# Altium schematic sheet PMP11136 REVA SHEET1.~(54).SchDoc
size 431 x 279 mm; Date: Not shown in title block; ApprovedBy: Not shown in title block; CheckedBy: Not shown in title block; Author: Not shown in title block; CompanyName: Not shown in title block; Engineer: Not shown in title block; Organization: Not shown in title block; Address1: Not shown in title block; Address2: Not shown in title block; Address3: Not shown in title block; Address4: Not shown in title block; DocumentNumber: 1; Revision: Use project parameter SCH_Rev; SheetNumber: 1; SheetTotal: 3; PageSetup: Record=PageOptions¦CenterHorizontal=True¦CenterVertical=True¦PrintScale=1.00¦XCorrection=1.00¦YCorrection=1.00¦PrintKind=0¦BorderSize=5000000¦LeftOffset=0¦BottomOffset=0¦Orientation=2¦PaperLength=1000¦PaperWidth=1000¦Scale=100¦PaperSource=15¦PrintQuality=600¦MediaType=1¦DitherType=10¦PaperKind=Letter¦PrintScaleMode=1
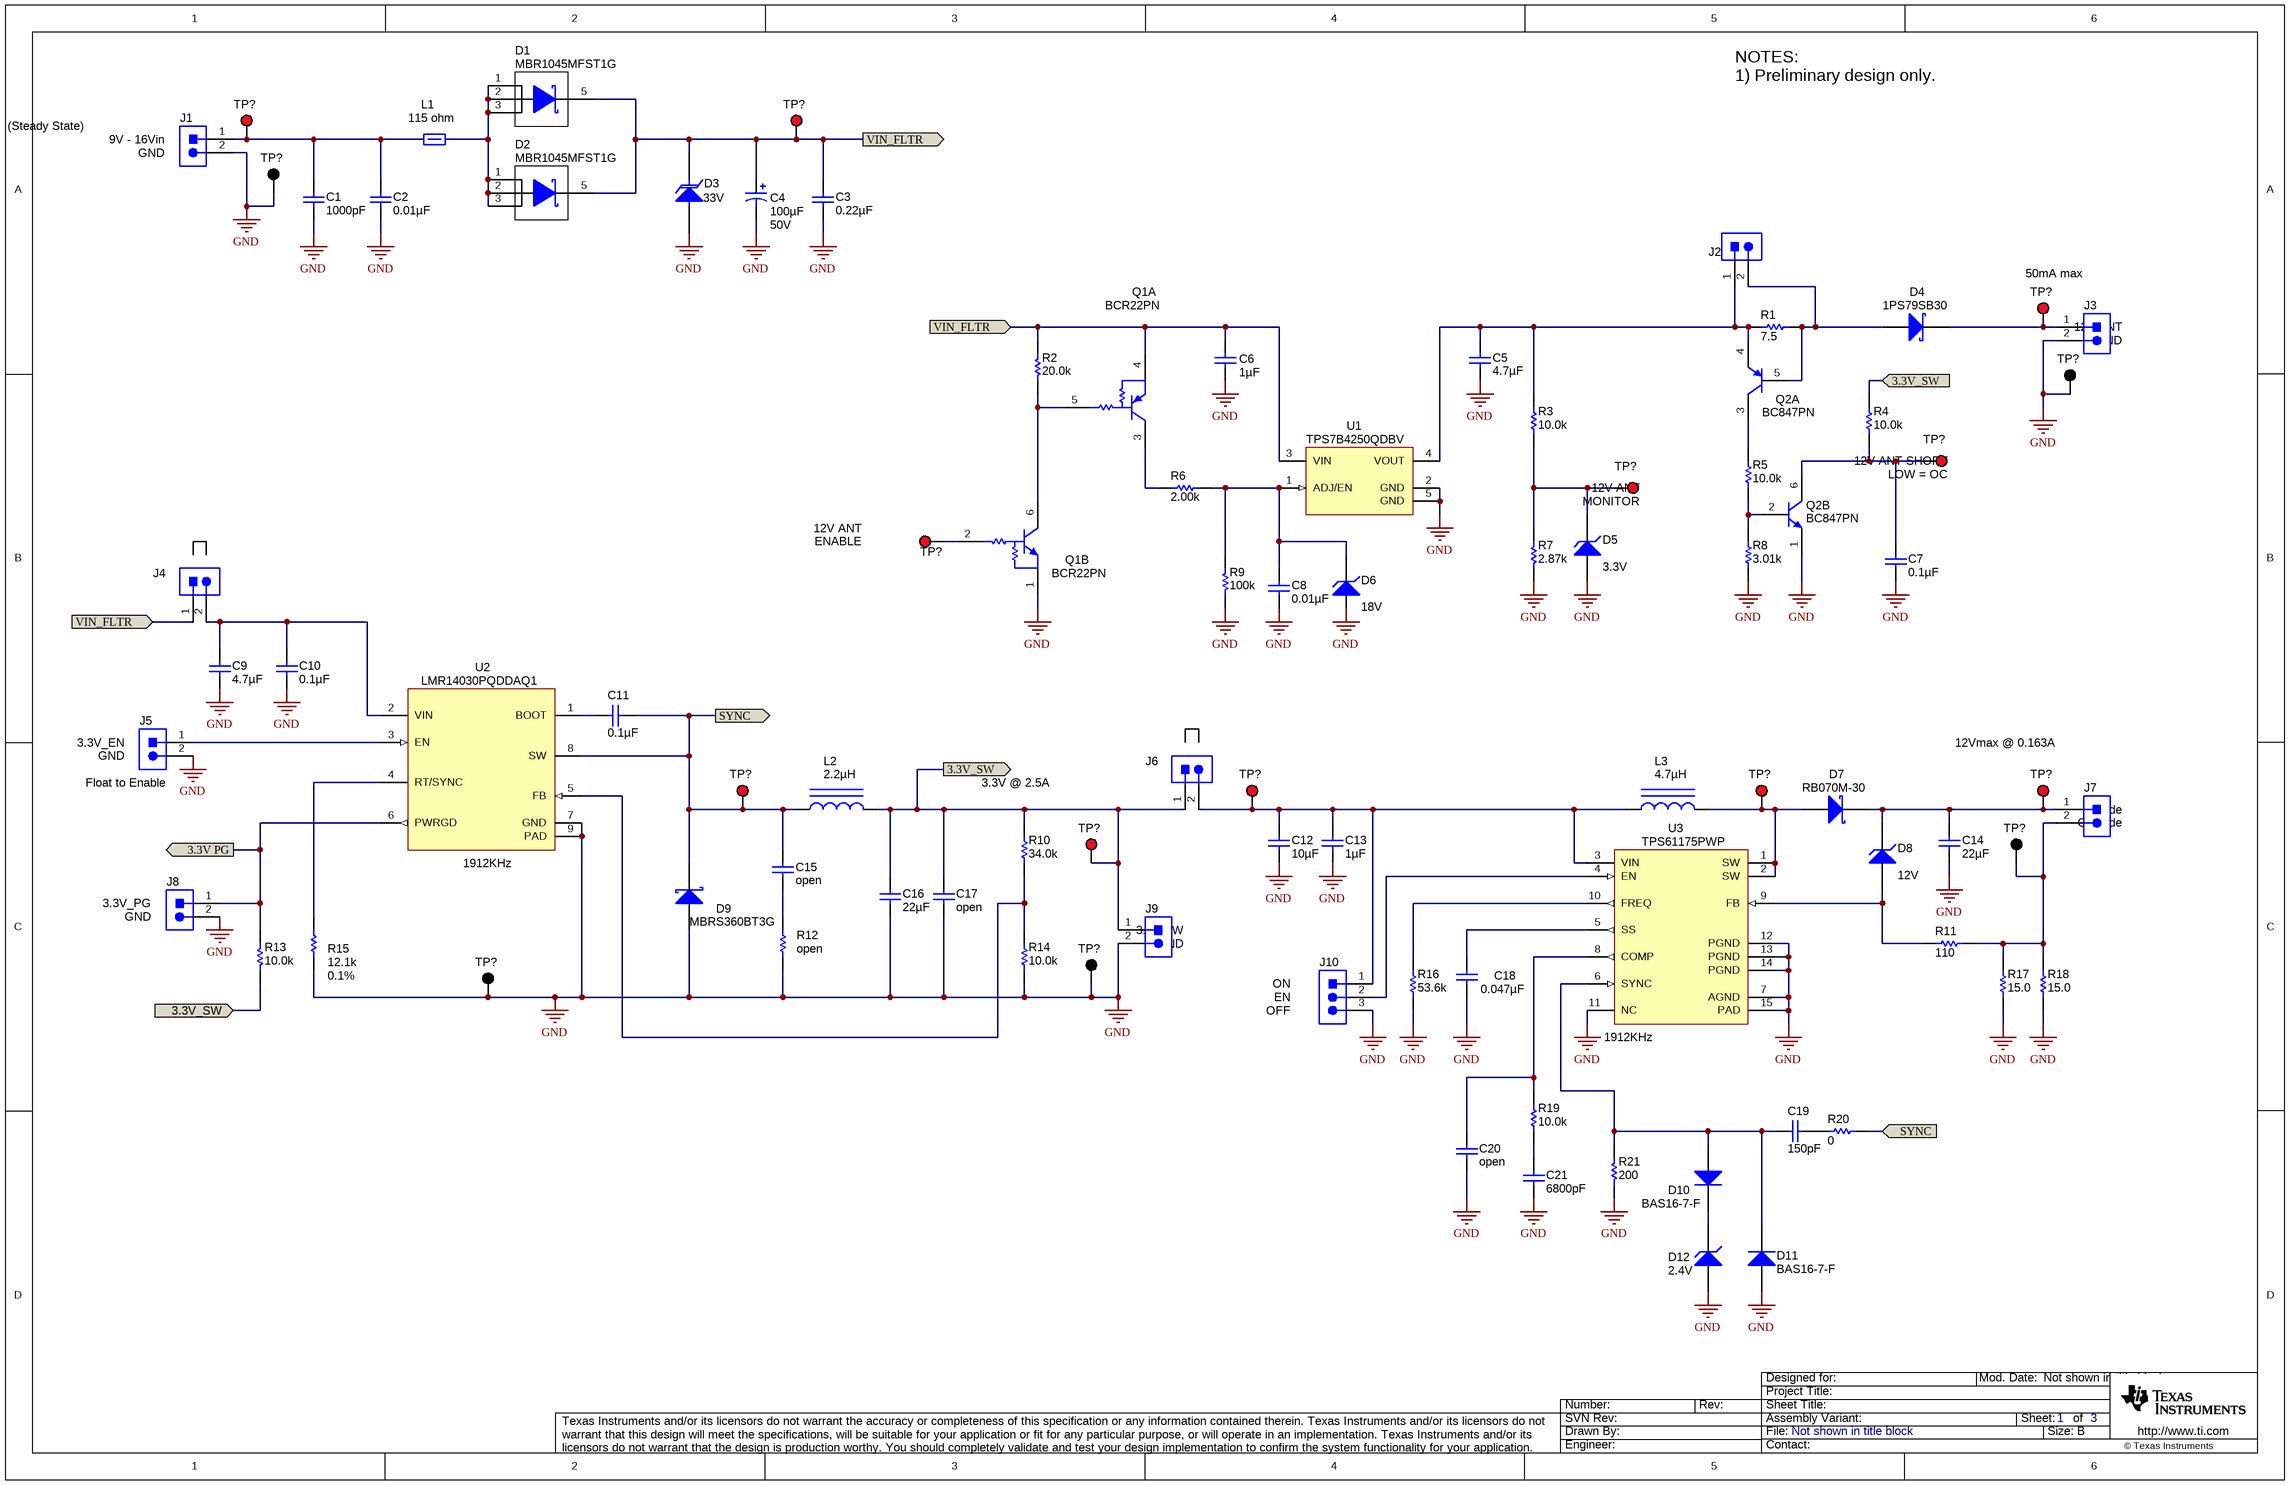
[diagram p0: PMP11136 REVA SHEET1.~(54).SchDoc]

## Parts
(Parts that share a designator on the sheet are numbered #1, #2 ... from top to bottom, then left to right.)
C1  ValueDisplayed: 1000pF  [0603]  (hidden comment: C1608C0G2A102J)
C2  ValueDisplayed: 0.01µF  [0603]  (hidden comment: C1608X7R2A103K)
C3  ValueDisplayed: 0.22µF  [0603]  (hidden comment: C1608X7R1H224K080AB)
C4  ValueDisplayed: 100µF  Value2: 50V  [SM_RADIAL_F]  (hidden comment: EEE-FK1H101P)
C5  ValueDisplayed: 4.7µF  [1210]  (hidden comment: C3225X7R1H475M250AB)
C6  ValueDisplayed: 1µF  [0603]  (hidden comment: C1608X7R1E105K)
C7  ValueDisplayed: 0.1µF  [0603]  (hidden comment: C1608X7R1H104K)
C8  ValueDisplayed: 0.01µF  [0603]  (hidden comment: C1608X7R1H103K)
C9  ValueDisplayed: 4.7µF  [1210]  (hidden comment: C3225X7R1H475M250AB)
C10  ValueDisplayed: 0.1µF  [0603]  (hidden comment: C1608X7R1H104K)
C11  ValueDisplayed: 0.1µF  [0603]  (hidden comment: C1608X7R1H104K)
C12  ValueDisplayed: 10µF  [0805]  (hidden comment: GRM21BR71A106KE51L)
C13  ValueDisplayed: 1µF  [0603]  (hidden comment: C1608X7R1E105K)
C14  ValueDisplayed: 22µF  [1210]  (hidden comment: C3225X7R1C226M250AC)
C15  ValueDisplayed: open  [0603]
C16  ValueDisplayed: 22µF  [1210]  (hidden comment: C3225X7R1C226M250AC)
C17  ValueDisplayed: open  [1210]
C18  ValueDisplayed: 0.047µF  [0603]  (hidden comment: C1608X7R1H473K)
C19  ValueDisplayed: 150pF  [0603]  (hidden comment: C1608C0G1H151J)
C20  ValueDisplayed: open  [0603]
C21  ValueDisplayed: 6800pF  [0603]  (hidden comment: C1608C0G1E682J)
D1  MBR1045MFST1G  [SO-8FL]
D2  MBR1045MFST1G  [SO-8FL]
D3  value 33V  [SMC]  (hidden comment: 1.5SMC33AT3G)
D4  1PS79SB30  [SOD-523]
D5  value 3.3V  [SOD-123]  (hidden comment: MMSZ4684T1G)
D6  value 18V  [SOD-123]  (hidden comment: MMSZ4705T1G)
D7  RB070M-30  [SOD-123]
D8  value 12V  [SOD-123]  (hidden comment: MMSZ4699T1G)
D9  MBRS360BT3G  [SMB]
D10  BAS16-7-F  [SOT-23]
D11  BAS16-7-F  [SOT-23]
D12  value 2.4V  [SOD-123]  (hidden comment: MMSZ5221B-7-F)
J1  ED555/2DS  [TERM_BLK_ED555-2DS]  (value not drawn)
J2  PEC02SAAN  [CONN_PEC02SAAN]  (value not drawn)
J3  ED555/2DS  [TERM_BLK_ED555-2DS]  (value not drawn)
J4  PEC02SAAN  [CONN_PEC02SAAN]  (value not drawn)
J5  PEC02SAAN  [CONN_PEC02SAAN]  (value not drawn)
J6  PEC02SAAN  [CONN_PEC02SAAN]  (value not drawn)
J7  ED555/2DS  [TERM_BLK_ED555-2DS]  (value not drawn)
J8  PEC02SAAN  [CONN_PEC02SAAN]  (value not drawn)
J9  ED555/2DS  [TERM_BLK_ED555-2DS]  (value not drawn)
J10  PEC03SAAN  [CONN_PEC03SAAN]  (value not drawn)
L1  value 115 ohm  [28F0181]  (hidden comment: 28F0181-1SR-10)
L2  ValueDisplayed: 2.2µH  [CLF6045NI-D]  (hidden comment: CLF6045NIT-2R2N-D)
L3  ValueDisplayed: 4.7µH  [CLF6045NI-D]  (hidden comment: CLF6045NIT-4R7N-D)
Q1  BCR22PN  [SOT-363]  (parts A,B of 2)
Q2  BC847PN  [SOT-363]  (parts A,B of 2)
R1  ValueDisplayed: 7.5  [2010]  (hidden comment: CRCW20107R50JNEF)
R2  ValueDisplayed: 20.0k  [0603]  (hidden comment: CRCW060320K0FKEA)
R3  ValueDisplayed: 10.0k  [0603]  (hidden comment: CRCW060310K0FKEA)
R4  ValueDisplayed: 10.0k  [0603]  (hidden comment: CRCW060310K0FKEA)
R5  ValueDisplayed: 10.0k  [0805_HV]  (hidden comment: CRCW080510K0FKEA)
R6  ValueDisplayed: 2.00k  [1206]  (hidden comment: CRCW12062K00FKEA)
R7  ValueDisplayed: 2.87k  [0603]  (hidden comment: CRCW06032K87FKEA)
R8  ValueDisplayed: 3.01k  [0603]  (hidden comment: CRCW06033K01FKEA)
R9  ValueDisplayed: 100k  [0603]  (hidden comment: CRCW0603100KFKEA)
R10  ValueDisplayed: 34.0k  [0603]  (hidden comment: CRCW060334K0FKEA)
R11  ValueDisplayed: 110  [0603]  (hidden comment: CRCW0603110RFKEA)
R12  value open  [2010]
R13  ValueDisplayed: 10.0k  [0603]  (hidden comment: CRCW060310K0FKEA)
R14  ValueDisplayed: 10.0k  [0603]  (hidden comment: CRCW060310K0FKEA)
R15  Value1: 0.1%  ValueDisplayed: 12.1k  [0603]
R16  ValueDisplayed: 53.6k  [0603]  (hidden comment: CRCW060353K6FKEA)
R17  ValueDisplayed: 15.0  [1206]  (hidden comment: CRCW120615R0FKEA)
R18  ValueDisplayed: 15.0  [1206]  (hidden comment: CRCW120615R0FKEA)
R19  ValueDisplayed: 10.0k  [0603]  (hidden comment: CRCW060310K0FKEA)
R20  ValueDisplayed: 0  [0603]  (hidden comment: CRCW06030000Z0EA)
R21  ValueDisplayed: 200  [0603]  (hidden comment: CRCW0603200RFKEA)
TP?#1  5000  [Keystone5000]  (value not drawn)
TP?#2  5000  [Keystone5000]  (value not drawn)
TP?#3  5001  [Keystone5001]  (value not drawn)
TP?#4  5000  [Keystone5000]  (value not drawn)
TP?#5  5001  [Keystone5001]  (value not drawn)
TP?#6  5000  [Keystone5000]  (value not drawn)
TP?#7  5000  [Keystone5000]  (value not drawn)
TP?#8  5000  [Keystone5000]  (value not drawn)
TP?#9  5000  [Keystone5000]  (value not drawn)
TP?#10  5000  [Keystone5000]  (value not drawn)
TP?#11  5000  [Keystone5000]  (value not drawn)
TP?#12  5000  [Keystone5000]  (value not drawn)
TP?#13  5000  [Keystone5000]  (value not drawn)
TP?#14  5001  [Keystone5001]  (value not drawn)
TP?#15  5001  [Keystone5001]  (value not drawn)
TP?#16  5001  [Keystone5001]  (value not drawn)
U1  TPS7B4250QDBV  [DBV0005A_N]
U2  LMR14030PQDDAQ1  [DDA0008E_N]
U3  TPS61175PWP  [PWP0014E_N]

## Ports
3.3V PG, 3.3V_SW, SYNC, VIN_FLTR

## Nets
GND: C1.2 C2.2 C3.2 C4.2(-) C5.1 C6.2 C7.2 C8.2 C9.1 C10.2 C12.2 C13.2 C14.2 C16.2 C17.2 C18.2 C20.2 C21.2 D3.2(A) D5.2(A) D9.2(A) D11.1(A) D12.2(A) J1.2 J3.2 J5.2 J8.2 J9.2 J10.3 Q1.1(E1) Q2.1(E) R7.2 R8.1 R9.2 R12.1 R14.1 R15.1 R16.1 R17.1 R18.1 R21.1 TP?#3.1 TP?#5.1 TP?#15.1 TP?#16.1 U1.2(GND) U1.5(GND) U2.7(GND) U2.9(PAD) U3.7(AGND) U3.11(NC) U3.12(PGND) U3.13(PGND) U3.14(PGND) U3.15(PAD)
3.3V PG: J8.1 R13.2 U2.6(PWRGD) ; port 3.3V PG
3.3V_SW: C16.1 C17.1 J6.1 J9.1 L2.2 R4.2 R10.2 R13.1 TP?#13.1 ; port 3.3V_SW
SYNC: C11.2 C15.1 D9.1(K) L2.1 R20.1 TP?#9.1 U2.8(SW) ; port SYNC
VIN_FLTR: C3.1 C4.1(+) C6.1 D1.5(K) D2.5(K) D3.1(K) J4.1 Q1.4(E2) R2.2 TP?#2.1 U1.3(VIN) ; port VIN_FLTR
NetC1_1: C1.1 C2.1 J1.1 L1.1 TP?#1.1
NetC5_2: C5.2 J2.1 Q2.4(E) R1.1 R3.2 U1.4(VOUT)
NetC7_1: C7.1 Q2.6(C) R4.1 TP?#6.1
NetC8_1: C8.1 D6.1(K) R6.2 R9.1 U1.1(ADJ/EN)
NetC9_2: C9.2 C10.1 J4.2 U2.2(VIN)
NetC11_1: C11.1 U2.1(BOOT)
NetC12_1: C12.1 C13.1 J6.2 J10.1 L3.1 TP?#10.1 U3.3(VIN)
NetC14_1: C14.1 D7.1(K) D8.1(K) J7.1 TP?#12.1
NetC15_2: C15.2 R12.2
NetC18_1: C18.1 U3.5(SS)
NetC19_1: C19.1 D10.1(A) D11.3(K) R21.2 U3.6(SYNC)
NetC19_2: C19.2 R20.2
NetC20_1: C20.1 R19.2 U3.8(COMP)
NetC21_1: C21.1 R19.1
NetD1_1: D1.1(A) D1.2(A) D1.3(A) D2.1(A) D2.2(A) D2.3(A) L1.2
NetD4_1: D4.1(K) J3.1 TP?#4.1
NetD4_2: D4.2(A) J2.2 Q2.5(B) R1.2
NetD5_1: D5.1(K) R3.1 R7.1 TP?#7.1
NetD7_2: D7.2(A) L3.2 TP?#11.1 U3.1(SW) U3.2(SW)
NetD8_2: D8.2(A) R11.2 U3.9(FB)
NetD10_3: D10.3(K) D12.1(K)
NetJ5_1: J5.1 U2.3(EN)
NetJ7_2: J7.2 R11.1 R17.2 R18.2 TP?#14.1
NetJ10_2: J10.2 U3.4(EN)
NetQ1_2: Q1.2(B1) TP?#8.1
NetQ1_3: Q1.3(C2) R6.1
NetQ1_5: Q1.5(B2) Q1.6(C1) R2.1
NetQ2_2: Q2.2(B) R5.1 R8.2
NetQ2_3: Q2.3(C) R5.2
NetR10_1: R10.1 R14.2 U2.5(FB)
NetR15_2: R15.2 U2.4(RT/SYNC)
NetR16_2: R16.2 U3.10(FREQ)

Not connected (* = marked no-connect by the designer): D6 2(A)

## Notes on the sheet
- (near J1) (Steady State)
- (near J1) 9V - 16Vin
- (near J1) GND
- NOTES:
  1) Preliminary design only.
- 50mA max
- (near J3) 12V ANT
- GND
- (near TP?#7) MONITOR
- (near TP?#7) 12V ANT
- (near TP?#6) LOW = OC
- (near TP?#6) 12V ANT SHORT
- (near TP?#8) ENABLE
- (near TP?#8) 12V ANT
- (near J5) 3.3V_EN
- (near J5) GND
- 12Vmax @ 0.163A
- (near J5) Float to Enable
- 3.3V @ 2.5A
- (near J7) Anode
- (near J7) Cathode
- (near J8) 3.3V_PG
- (near U2) 1912KHz
- (near J8) GND
- (near J9) 3.3V SW
- (near J9) GND
- (near J10) ON
- (near J10) EN
- (near J10) OFF
- (near U3) 1912KHz
- Labels drawn without touching a wire or pin: GND

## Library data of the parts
C1 = C1608C0G2A102J: CAP, CERM, 1000 pF, 100 V, +/- 5%, C0G/NP0, 0603; Manufacturer: TDK; Polarized: N; CompType: Capacitor; Value: 1000pF; U/M: EA; Cap_F: 0.000000001; Tolerance_%: 5; ESR_ohm: 0.0589; Value1: 0.0589 ohm; VDC_V: 100; Value2: 100V; TaMin_C: -55; TaMax_C: 125
C2 = C1608X7R2A103K: CAP, CERM, 0.01 µF, 100 V, +/- 10%, X7R, 0603; Manufacturer: TDK; Polarized: N; CompType: Capacitor; Value: 0.01uF; U/M: EA; Cap_F: 0.00000001; Tolerance_%: 10; ESR_ohm: 0.0661; Value1: 0.0661 ohm; VDC_V: 100; Value2: 100V; TaMin_C: -55; TaMax_C: 125
C3 = C1608X7R1H224K080AB: CAP, CERM, 0.22 µF, 50 V, +/- 10%, X7R, 0603; Manufacturer: TDK; Polarized: N; CompType: Capacitor; Value: 0.22uF; U/M: EA; Cap_F: 0.00000022; Tolerance_%: 10; Value1: Unknown; VDC_V: 50; Value2: 50V; TaMin_C: -55; TaMax_C: 125
C4 = EEE-FK1H101P: CAP, AL, 100 µF, 50 V, +/- 20%, 0.34 ohm, SMD; Manufacturer: Panasonic; Polarized: Y; CompType: Capacitor; Value: 100uF; U/M: EA; Cap_F: 0.0001; Tolerance_%: 20; VDC_V: 50; ESR_ohm: 0.34; IRMS_A: 0.35; TaMin_C: -55; TaMax_C: 105; Cap_Case: F
C5 C9 = C3225X7R1E106M: CAP, CERM, 4.7uF, 50V, +/-20%, X7R, 1210; Manufacturer: TDK; Polarized: N; CompType: Capacitor; U/M: EA; Cap_F: 0.00001; Tolerance_%: 20; ESR_Ohm: 0.0027; Value1: 0.0027 ohm; VDC_V: 50; IRMS_A: 3; TaMin_C: -55; TaMax_C: 125
C6 C13 = C1608X7R1C105K: CAP, CERM, 1uF, 25V, +/-10%, X7R, 0603; Manufacturer: TDK; Polarized: N; CompType: Capacitor; U/M: EA; Cap_F: 0.000001; Tolerance_%: 10; ESR_Ohm: 0.0057; Value1: 0.0057 ohm; VDC_V: 25; TaMin_C: -55; TaMax_C: 125
C7 C10 C11 = C1608X7R1H104K: CAP, CERM, 0.1uF, 50V, +/-10%, X7R, 0603; Manufacturer: TDK; Polarized: N; CompType: Capacitor; U/M: EA; Cap_F: 0.0000001; Tolerance_%: 10; ESR_Ohm: 0.017; Value1: 0.017 ohm; VDC_V: 50; TaMin_C: -55; TaMax_C: 125
C8 = C1608X7R1H103K: CAP, CERM, 0.01 µF, 50 V, +/- 10%, X7R, 0603; Manufacturer: TDK; Polarized: N; CompType: Capacitor; Value: 0.01uF; U/M: EA; Cap_F: 0.00000001; Tolerance_%: 10; ESR_ohm: 0.0539; Value1: 0.0539 ohm; VDC_V: 50; Value2: 50V; TaMin_C: -55; TaMax_C: 125
C12 = GRM21BR71A106KE51L: CAP, CERM, 10uF, 10V, +/-10%, X7R, 0805; Manufacturer: MuRata; Polarized: N; CompType: Capacitor; U/M: EA; Cap_F: 0.00001; Tolerance_%: 10; ESR_Ohm: 0.003; Value1: 0.003 ohm; TaMin_C: -55; TaMax_C: 125
C14 C16 = C3225X7R1C226M: CAP, CERM, 22 µF, 16 V, +/- 20%, X7R, 1210; Manufacturer: TDK; Polarized: N; CompType: Capacitor; Value: 22uF; U/M: EA; Cap_F: 0.000022; Tolerance_%: 20; ESR_ohm: 0.002; Value1: 0.002 ohm; VDC_V: 16; Value2: 16V; IRMS_A: 8.11; TaMin_C: -55; TaMax_C: 125
C15 C20 = C1608C0G1H102J: CAP, CERM, open, 0603; Polarized: N; CompType: Capacitor; U/M: EA; Cap_F: 0.000000001; Tolerance_%: 5; ESR_ohm: 0.0563; TempCo: C0G/NP0; TaMin_C: -55; TaMax_C: 125
C17 = C3225X7R1C226M: CAP, open, 1210; Polarized: N; CompType: Capacitor; U/M: EA; Cap_F: 0.000022; Tolerance_%: 20; ESR_ohm: 0.002; TempCo: X7R; IRMS_A: 8.11; TaMin_C: -55; TaMax_C: 125
C18 = C1608X7R1H473K: CAP, CERM, 0.047 µF, 50 V, +/- 10%, X7R, 0603; Manufacturer: TDK; Polarized: N; CompType: Capacitor; Value: 0.047uF; U/M: EA; Cap_F: 0.000000047; Tolerance_%: 10; ESR_ohm: 0.0234; Value1: 0.0234 ohm; VDC_V: 50; Value2: 50V; TaMin_C: -55; TaMax_C: 125
C19 = C1608C0G1H151J: CAP, CERM, 150 pF, 50 V, +/- 5%, C0G/NP0, 0603; Manufacturer: TDK; Polarized: N; CompType: Capacitor; Value: 150pF; U/M: EA; Cap_F: 0.00000000015; Tolerance_%: 5; ESR_ohm: 0.1084; Value1: 0.1084 ohm; VDC_V: 50; Value2: 50V; TaMin_C: -55; TaMax_C: 125
C21 = C1608C0G1E682J: CAP, CERM, 6800 pF, 25 V, +/- 5%, C0G/NP0, 0603; Manufacturer: TDK; Polarized: N; CompType: Capacitor; Value: 6800pF; U/M: EA; Cap_F: 0.0000000068; Tolerance_%: 5; Value1: Unknown; VDC_V: 25; Value2: 25V; TaMin_C: -55; TaMax_C: 125
D1 D2 = MBR1045MFST1G: Diode, Schottky, 45 V, 10 A, 6.15x1.00x5.15mm; Manufacturer: ON Semiconductor; SymbolCreator: a0411947; U/M: EA; Vf_V: 0.62; Value: 45V; Value1: 10A; Value2: 0.62V; Io_A: 10; Vr_V: 45; TJmax_C: 150; RJC_CperW: 1.7
D3 = 1.5SMC6.8A: Diode, TVS, Uni, 33 V, 1500 W, SMC; Manufacturer: Littelfuse; U/M: EA; Power_W: 1500; Vr_V: 33; Value1: 1500W; RJA_CperW: 75
D4 = 1PS79SB70,115: Diode, Schottky, 30 V, 0.2 A, SOD-523; Manufacturer: NXP; U/M: EA; Value: 30V; Value1: 0.2A; Io_A: 0.07; TJmax_C: 150
D5 = MMSZ4684T1G: Diode, Zener, 3.3 V, 500 mW, SOD-123; Manufacturer: ON Semiconductor; SymbolCreator: a0412235; U/M: EA; Power_W: 0.5; Vz_V: 3.3; Value1: 0.5W; RJA_CperW: 340
D6 = MMSZ4705T1G: Diode, Zener, 18 V, 500 mW, SOD-123; Manufacturer: ON Semiconductor; SymbolCreator: a0412235; U/M: EA; Power_W: 0.5; Vz_V: 18; Value1: 0.5W; RJA_CperW: 340
D7 = B130LAW-7-F: Diode, Schottky, 30V, 1.5A, SOD-123; Manufacturer: Rohm; U/M: EA; Vf_V: 0.38; Value1: 1A; Value2: 0.38V; Io_A: 1.5; Vr_V: 30; TJmax_C: 125
D8 = MMSZ4699T1G: Diode, Zener, 12 V, 500 mW, SOD-123; Manufacturer: ON Semiconductor; SymbolCreator: a0412235; U/M: EA; Power_W: 0.5; Vz_V: 12; Value1: 0.5W; RJA_CperW: 340
D9 = MBRS260T3G: Diode, Schottky, 60V, 3A, SMB; Manufacturer: ON Semiconductor; U/M: EA; Vf_V: 0.63; Value2: 0.63V; Io_A: 2; Vr_V: 60; TJmax_C: 125; RJC_CperW: 24
D10 D11 = BAS16-7-F: Diode, Ultrafast, 75V, 0.3A, SOT-23; Manufacturer: Diodes Inc.; U/M: EA; Vf_V: 1.125; Value2: 1.125V; Io_A: 0.3; Vr_V: 75
D12 = MMSZ5221B-7-F: Diode, Zener, 2.4V, 500 mW, SOD-123; Manufacturer: Diodes Inc.; SymbolCreator: a0412235; U/M: EA; Power_W: 0.5; Vz_V: 2.4; Value1: 0.5W; RJA_CperW: 350
J1 J3 J7 J9 = ED555/2DS: Terminal Block, 6A, 3.5mm Pitch, 2-Pos, TH; Manufacturer: On-Shore Technology; SymbolCreator: a0412235; CompType: Connector; U/M: EA
J2 J4-J6 J8 = PEC02SAAN: Header, 100mil, 2x1, Tin, TH; Manufacturer: Sullins Connector Solutions; SymbolCreator: a0412235; U/M: EA
J10 = PEC03SAAN: Header, 100mil, 3x1, Tin, TH; Manufacturer: Sullins Connector Solutions; SymbolCreator: a0799628; U/M: EA
L1 = 28F0181-1SR-10: Ferrite Bead, 115 ohm @ 100MHz, 10A, SMD, 2-Leads, Body 8.74x4.65mm; Manufacturer: Laird-Signal Integrity Products; Imax_A: 10; DCR_ohm: 0.001; Value1: 0.001 ohm; ZTyp@100MHz_Ohm: 115
L2 = CLF6045NIT-2R2N-D: Inductor, Wirewound, Ferrite, 2.2 µH, 4.1 A, 0.015 ohm, SMD; Manufacturer: TDK; Value: 2.2uH; Ind_H: 2.2E-6; Imax_A: 4.1; Irms: 4.1A @ 40C rise; Isat: 4.2A @ 30% inductance drop; DCR_ohm: 0.015; Value2: 4.1A
L3 = CLF6045NIT-4R7N-D: Inductor, Wirewound, Ferrite, 4.7 µH, 3.1 A, 0.023 ohm, SMD; Manufacturer: TDK; Value: 4.7uH; Ind_H: 4.7E-6; Imax_A: 3.1; Irms: 3.3A @ 40C rise; Isat: 3.1A @ 30% inductance drop; DCR_ohm: 0.023; Value2: 3.1A
Q1 = BCR 48PN E6327, Infineon Technologies: Transistor, NPN/PNP Pair, 50 V, 0.1 A, SOT-363; SymbolCreator: Altium; PNP: 1; Vceo_V: 50; Vcesat1_V: 0.3; Value: 50 V; IcRated_A: 0.07; Value1: 0.1 A; TaMin_C: -65; TaMax_C: 150; CompType: BJT; U/M: EA
Q2 = BC 846PN H6327, Infineon Technologies: Transistor, NPN/PNP Pair, 45 V, 0.1 A, SOT-363; SymbolCreator: a0411947; PNP: 1; Vceo_V: 45; Vcesat1_V: 0.2; Value: 45 V; IcRated_A: 0.1; Value1: 0.1 A; HfeMax: 450; TaMin_C: -65; TaMax_C: 150; CompType: BJT; U/M: EA
R1 = CRCW20107R50JNEF: RES, 7.5, 5%, 0.75 W, 2010; Manufacturer: Vishay-Dale; CompType: Resistor; Value: 7.5; Value_Code: 7R50; Tolerance_%: 5; Power_W: 0.75; Value2: 0.75W; VDC_V: 400; TempCo: 200 ppm/C; EIA_Code: E24; U/M: EA
R2 = CRCW060320K0FKEA: RES, 20.0 k, 1%, 0.1 W, 0603; Manufacturer: Vishay-Dale; CompType: Resistor; Value: 20.0k; Res_ohm: 20000; Value_Code: 20k0; Tolerance_%: 1; Power_W: 0.1; Value2: 0.1W; VDC_V: 75; TempCo: 100 ppm/C; EIA_Code: E96; U/M: EA
R3 R4 R13 R14 R19 = CRCW060310K0FKEA: RES, 10.0 k, 1%, 0.1 W, 0603; Manufacturer: Vishay-Dale; CompType: Resistor; Value: 10.0k; Res_ohm: 10000; Value_Code: 10k0; Tolerance_%: 1; Power_W: 0.1; Value2: 0.1W; VDC_V: 75; TempCo: 100 ppm/C; EIA_Code: E96; U/M: EA
R5 = CRCW080510K0FKEA: RES, 10.0 k, 1%, 0.125 W, 0805; Manufacturer: Vishay-Dale; CompType: Resistor; Value: 10.0k; Res_ohm: 10000; Value_Code: 10k0; Tolerance_%: 1; Power_W: 0.125; Value2: 0.125W; VDC_V: 150; TempCo: 100 ppm/C; EIA_Code: E96; U/M: EA
R6 = CRCW12062K00FKEA: RES, 2.00 k, 1%, 0.25 W, 1206; Manufacturer: Vishay-Dale; CompType: Resistor; Value: 2.00k; Res_ohm: 2000; Value_Code: 2k00; Tolerance_%: 1; Power_W: 0.25; Value2: 0.25W; VDC_V: 200; TempCo: 100 ppm/C; EIA_Code: E96; U/M: EA
R7 = CRCW06032K87FKEA: RES, 2.87 k, 1%, 0.1 W, 0603; Manufacturer: Vishay-Dale; CompType: Resistor; Value: 2.87k; Res_ohm: 2870; Value_Code: 2k87; Tolerance_%: 1; Power_W: 0.1; Value2: 0.1W; VDC_V: 75; TempCo: 100 ppm/C; EIA_Code: E96; U/M: EA
R8 = CRCW06033K01FKEA: RES, 3.01 k, 1%, 0.1 W, 0603; Manufacturer: Vishay-Dale; CompType: Resistor; Value: 3.01k; Res_ohm: 3010; Value_Code: 3k01; Tolerance_%: 1; Power_W: 0.1; Value2: 0.1W; VDC_V: 75; TempCo: 100 ppm/C; EIA_Code: E96; U/M: EA
R9 = CRCW0603100KFKEA: RES, 100 k, 1%, 0.1 W, 0603; Manufacturer: Vishay-Dale; CompType: Resistor; Value: 100k; Res_ohm: 100000; Tolerance_%: 1; Power_W: 0.1; Value2: 0.1W; VDC_V: 75; TempCo: 100 ppm/C; EIA_Code: E96; U/M: EA
R10 = CRCW060334K0FKEA: RES, 34.0 k, 1%, 0.1 W, 0603; Manufacturer: Vishay-Dale; CompType: Resistor; Value: 34.0k; Res_ohm: 34000; Value_Code: 34k0; Tolerance_%: 1; Power_W: 0.1; Value2: 0.1W; VDC_V: 75; TempCo: 100 ppm/C; EIA_Code: E96; U/M: EA
R11 = CRCW0603110RFKEA: RES, 110, 1%, 0.1 W, 0603; Manufacturer: Vishay-Dale; CompType: Resistor; Value: 110; Value_Code: 110R; Tolerance_%: 1; Power_W: 0.1; Value2: 0.1W; VDC_V: 75; TempCo: 100 ppm/C; EIA_Code: E96; U/M: EA
R12 = CRCW20102R70JNEF: RES, open, 2010; CompType: Resistor; Tolerance_%: 5; Power_W: 0.75; TempCo: 200 ppm/C; EIA_Code: E24; U/M: EA
R15 = CRCW060312K1FKEA: RES, 12.1 k, 0.1%, 0.1 W, 0603; Manufacturer: Vishay-Dale; CompType: Resistor; Value: 12.1k; Res_ohm: 12100; Value_Code: 12k1; Tolerance_%: 1; Power_W: 0.1; Value2: 0.1W; VDC_V: 75; TempCo: 100 ppm/C; EIA_Code: E96; U/M: EA
R16 = CRCW060353K6FKEA: RES, 53.6 k, 1%, 0.1 W, 0603; Manufacturer: Vishay-Dale; CompType: Resistor; Value: 53.6k; Res_ohm: 53600; Value_Code: 53k6; Tolerance_%: 1; Power_W: 0.1; Value2: 0.1W; VDC_V: 75; TempCo: 100 ppm/C; EIA_Code: E96; U/M: EA
R17 R18 = CRCW120615R0FKEA: RES, 15.0, 1%, 0.25 W, 1206; Manufacturer: Vishay-Dale; CompType: Resistor; Value: 15.0; Res_ohm: 15; Value_Code: 15R0; Tolerance_%: 1; Power_W: 0.25; Value2: 0.25W; VDC_V: 200; TempCo: 100 ppm/C; EIA_Code: E96; U/M: EA
R20 = CRCW06030000Z0EA: RES, 0, 5%, 0.1 W, 0603; Manufacturer: Vishay-Dale; CompType: Resistor; Value: 0; Value_Code: 0000; Tolerance_%: 5; Power_W: 0.1; Value2: 0.1W; VDC_V: 75; TempCo: 200 ppm/C; EIA_Code: E24; U/M: EA
R21 = CRCW0603200RFKEA: RES, 200, 1%, 0.1 W, 0603; Manufacturer: Vishay-Dale; CompType: Resistor; Value: 200; Value_Code: 200R; Tolerance_%: 1; Power_W: 0.1; Value2: 0.1W; VDC_V: 75; TempCo: 100 ppm/C; EIA_Code: E96; U/M: EA
TP?#1 TP?#2 TP?#4 TP?#6-TP?#13 = 5000: Test Point, Miniature, Red, TH; Manufacturer: Keystone; CompType: Test Point Loop; U/M: EA
TP?#3 TP?#5 TP?#14-TP?#16 = 5001: Test Point, Miniature, Black, TH; Manufacturer: Keystone; CompType: Test Point Loop; U/M: EA
U1 = TPS7B4250QDBV: Low Dropout Voltage Tracking LDO, DBV0005A; Manufacturer: Texas Instruments; SymbolCreator: a0411947; CompType: IC; U/M: EA
U2 = LMR14030PDDAR: LMR14030PQDDAQ1, DDA0008E; Manufacturer: Texas Instruments; SymbolCreator: Altium; CompType: IC; U/M: EA
U3 = TPS61175PWP: 3-A High Voltage Boost Converter with Soft-start and Programmable Switching Frequency, PWP0014E; Manufacturer: Texas Instruments; SymbolCreator: a0411947; CompType: IC; U/M: EA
